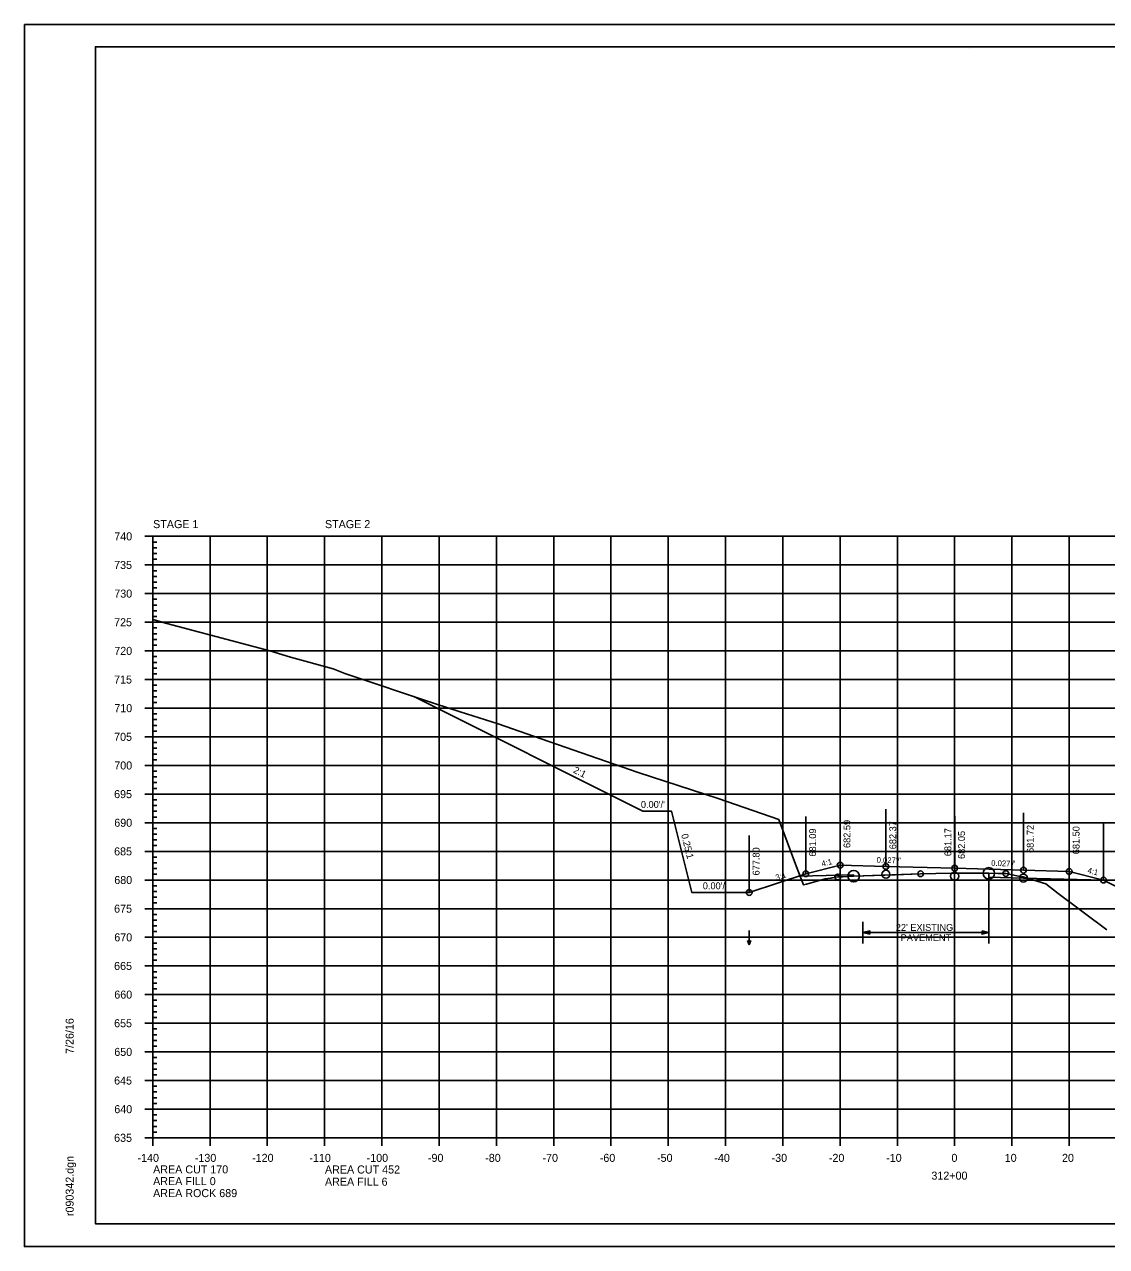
# Model space of a CAD drawing. Extents: x 1370515 to 1370849, y 383299 to 386073.
# Drawn here: x 1370515.4 to 1370704.3, y 385219.5 to 385432.8 of the extents above; entities that cross this region are included whole.
import ezdxf

# ---------------------------------------------------------------- set-up
doc = ezdxf.new("R2010")
doc.units = 0
for name, color, linetype in [('R_Alt Surface', 7, 'Continuous'), ('R_Axis', 7, 'Continuous'), ('R_Axis Annot', 7, 'Continuous'), ('R_Border', 7, 'Continuous'), ('R_Detour', 7, 'Continuous'), ('R_Exist Surface', 7, 'Continuous'), ('R_Fin Surface', 7, 'Continuous'), ('R_Grid', 7, 'Continuous'), ('R_No Plot', 7, 'Continuous'), ('R_ROW Annot', 7, 'Continuous'), ('R_Water', 7, 'Continuous'), ('R_Water Annot', 7, 'Continuous'), ('R_Xsect Elev', 7, 'Continuous'), ('R_Xsect Slope', 7, 'Continuous')]:
    doc.layers.add(name, color=color, linetype=linetype)

msp = doc.modelspace()

# ---------------------------------------------------------------- linework, layer by layer
at = {"layer": 'R_Alt Surface'}
msp.add_lwpolyline([(1370650.61, 385284.14), (1370660.16, 385284.33), (1370660.16, 385284.12), (1370671.86, 385284.55), (1370677.21, 385284.62), (1370683.77, 385284.62), (1370683.77, 385283.96), (1370689.8, 385283.79), (1370703.89, 385283.41)], dxfattribs=at)
at = {"layer": 'R_Axis'}
for p, q in [((1370536.4, 385343.45), (1370539.2, 385343.45)), ((1370537.8, 385238.45), (1370537.8, 385343.45)), ((1370537.8, 385342.45), (1370538.5, 385342.45)), ((1370537.8, 385341.45), (1370538.5, 385341.45)), ((1370537.8, 385340.45), (1370538.5, 385340.45)), ((1370537.8, 385339.45), (1370538.5, 385339.45)), ((1370536.4, 385338.45), (1370539.2, 385338.45)), ((1370537.8, 385337.45), (1370538.5, 385337.45)), ((1370537.8, 385336.45), (1370538.5, 385336.45)), ((1370537.8, 385335.45), (1370538.5, 385335.45)), ((1370536.4, 385333.45), (1370539.2, 385333.45)), ((1370537.8, 385334.45), (1370538.5, 385334.45)), ((1370537.8, 385332.45), (1370538.5, 385332.45)), ((1370537.8, 385331.45), (1370538.5, 385331.45)), ((1370537.8, 385330.45), (1370538.5, 385330.45)), ((1370536.4, 385328.45), (1370539.2, 385328.45)), ((1370537.8, 385329.45), (1370538.5, 385329.45)), ((1370537.8, 385327.45), (1370538.5, 385327.45)), ((1370537.8, 385326.45), (1370538.5, 385326.45)), ((1370537.8, 385325.45), (1370538.5, 385325.45)), ((1370537.8, 385324.45), (1370538.5, 385324.45)), ((1370536.4, 385323.45), (1370539.2, 385323.45)), ((1370537.8, 385322.45), (1370538.5, 385322.45)), ((1370537.8, 385321.45), (1370538.5, 385321.45)), ((1370537.8, 385320.45), (1370538.5, 385320.45)), ((1370536.4, 385318.45), (1370539.2, 385318.45)), ((1370537.8, 385319.45), (1370538.5, 385319.45)), ((1370537.8, 385317.45), (1370538.5, 385317.45)), ((1370537.8, 385316.45), (1370538.5, 385316.45)), ((1370537.8, 385315.45), (1370538.5, 385315.45)), ((1370536.4, 385313.45), (1370539.2, 385313.45)), ((1370537.8, 385314.45), (1370538.5, 385314.45)), ((1370537.8, 385312.45), (1370538.5, 385312.45)), ((1370537.8, 385311.45), (1370538.5, 385311.45)), ((1370537.8, 385310.45), (1370538.5, 385310.45)), ((1370537.8, 385309.45), (1370538.5, 385309.45)), ((1370536.4, 385308.45), (1370539.2, 385308.45)), ((1370537.8, 385307.45), (1370538.5, 385307.45)), ((1370537.8, 385306.45), (1370538.5, 385306.45)), ((1370537.8, 385305.45), (1370538.5, 385305.45)), ((1370536.4, 385303.45), (1370539.2, 385303.45)), ((1370537.8, 385304.45), (1370538.5, 385304.45)), ((1370537.8, 385302.45), (1370538.5, 385302.45)), ((1370537.8, 385301.45), (1370538.5, 385301.45)), ((1370536.4, 385298.45), (1370539.2, 385298.45)), ((1370537.8, 385300.45), (1370538.5, 385300.45)), ((1370537.8, 385299.45), (1370538.5, 385299.45)), ((1370537.8, 385297.45), (1370538.5, 385297.45)), ((1370537.8, 385296.45), (1370538.5, 385296.45)), ((1370537.8, 385295.45), (1370538.5, 385295.45)), ((1370537.8, 385294.45), (1370538.5, 385294.45)), ((1370536.4, 385293.45), (1370539.2, 385293.45)), ((1370537.8, 385292.45), (1370538.5, 385292.45)), ((1370537.8, 385291.45), (1370538.5, 385291.45)), ((1370537.8, 385290.45), (1370538.5, 385290.45)), ((1370536.4, 385288.45), (1370539.2, 385288.45)), ((1370537.8, 385289.45), (1370538.5, 385289.45)), ((1370537.8, 385287.45), (1370538.5, 385287.45)), ((1370537.8, 385286.45), (1370538.5, 385286.45)), ((1370536.4, 385283.45), (1370539.2, 385283.45)), ((1370537.8, 385285.45), (1370538.5, 385285.45)), ((1370537.8, 385284.45), (1370538.5, 385284.45)), ((1370537.8, 385282.45), (1370538.5, 385282.45)), ((1370537.8, 385281.45), (1370538.5, 385281.45)), ((1370537.8, 385280.45), (1370538.5, 385280.45)), ((1370537.8, 385279.45), (1370538.5, 385279.45)), ((1370536.4, 385278.45), (1370539.2, 385278.45)), ((1370537.8, 385277.45), (1370538.5, 385277.45)), ((1370537.8, 385276.45), (1370538.5, 385276.45)), ((1370537.8, 385275.45), (1370538.5, 385275.45)), ((1370536.4, 385273.45), (1370539.2, 385273.45)), ((1370537.8, 385274.45), (1370538.5, 385274.45)), ((1370537.8, 385272.45), (1370538.5, 385272.45)), ((1370537.8, 385271.45), (1370538.5, 385271.45)), ((1370537.8, 385270.45), (1370538.5, 385270.45)), ((1370537.8, 385269.45), (1370538.5, 385269.45)), ((1370536.4, 385268.45), (1370539.2, 385268.45)), ((1370537.8, 385267.45), (1370538.5, 385267.45)), ((1370537.8, 385266.45), (1370538.5, 385266.45)), ((1370537.8, 385265.45), (1370538.5, 385265.45)), ((1370537.8, 385264.45), (1370538.5, 385264.45)), ((1370536.4, 385263.45), (1370539.2, 385263.45)), ((1370537.8, 385262.45), (1370538.5, 385262.45)), ((1370537.8, 385261.45), (1370538.5, 385261.45)), ((1370537.8, 385260.45), (1370538.5, 385260.45)), ((1370536.4, 385258.45), (1370539.2, 385258.45)), ((1370537.8, 385259.45), (1370538.5, 385259.45)), ((1370537.8, 385257.45), (1370538.5, 385257.45)), ((1370537.8, 385256.45), (1370538.5, 385256.45)), ((1370537.8, 385255.45), (1370538.5, 385255.45)), ((1370537.8, 385254.45), (1370538.5, 385254.45)), ((1370536.4, 385253.45), (1370539.2, 385253.45)), ((1370537.8, 385252.45), (1370538.5, 385252.45)), ((1370537.8, 385251.45), (1370538.5, 385251.45)), ((1370537.8, 385250.45), (1370538.5, 385250.45)), ((1370537.8, 385249.45), (1370538.5, 385249.45)), ((1370536.4, 385248.45), (1370539.2, 385248.45)), ((1370537.8, 385247.45), (1370538.5, 385247.45)), ((1370537.8, 385246.45), (1370538.5, 385246.45)), ((1370537.8, 385245.45), (1370538.5, 385245.45)), ((1370536.4, 385243.45), (1370539.2, 385243.45)), ((1370537.8, 385244.45), (1370538.5, 385244.45)), ((1370537.8, 385242.45), (1370538.5, 385242.45)), ((1370537.8, 385241.45), (1370538.5, 385241.45)), ((1370537.8, 385240.45), (1370538.5, 385240.45)), ((1370537.8, 385237.05), (1370537.8, 385239.85)), ((1370537.8, 385239.45), (1370538.5, 385239.45)), ((1370547.8, 385237.05), (1370547.8, 385239.85)), ((1370557.8, 385237.05), (1370557.8, 385239.85)), ((1370567.8, 385237.05), (1370567.8, 385239.85)), ((1370577.8, 385237.05), (1370577.8, 385239.85)), ((1370587.8, 385237.05), (1370587.8, 385239.85)), ((1370597.8, 385237.05), (1370597.8, 385239.85)), ((1370607.8, 385237.05), (1370607.8, 385239.85)), ((1370617.8, 385237.05), (1370617.8, 385239.85)), ((1370627.8, 385237.05), (1370627.8, 385239.85)), ((1370637.8, 385237.05), (1370637.8, 385239.85)), ((1370647.8, 385237.05), (1370647.8, 385239.85)), ((1370657.8, 385237.05), (1370657.8, 385239.85)), ((1370667.8, 385237.05), (1370667.8, 385239.85)), ((1370677.8, 385237.05), (1370677.8, 385239.85)), ((1370687.8, 385237.05), (1370687.8, 385239.85)), ((1370697.8, 385237.05), (1370697.8, 385239.85)), ((1370536.4, 385238.45), (1370539.2, 385238.45)), ((1370537.8, 385238.45), (1370817.8, 385238.45))]:
    msp.add_line(p, q, dxfattribs=at)
at = {"layer": 'R_Border'}
for p, q in [((1370527.8, 385428.91), (1370843.98, 385428.91)), ((1370527.8, 385223.45), (1370527.8, 385428.91)), ((1370680.32, 385428.65), (1370680.32, 385428.65)), ((1370680.32, 385428.65), (1370680.32, 385428.65)), ((1370527.8, 385223.45), (1370527.8, 385223.45)), ((1370843.98, 385223.45), (1370527.8, 385223.45))]:
    msp.add_line(p, q, dxfattribs=at)
at = {"layer": 'R_Exist Surface'}
msp.add_lwpolyline([(1370537.8, 385328.93), (1370539.26, 385328.51), (1370539.31, 385328.5), (1370539.41, 385328.47), (1370558.21, 385323.45), (1370561.83, 385322.37), (1370569.27, 385320.31), (1370571.36, 385319.51), (1370586.97, 385314.24), (1370591.49, 385312.81), (1370598.08, 385310.72), (1370605.58, 385308.09), (1370622.53, 385302.22), (1370636.49, 385297.7), (1370647.09, 385293.99), (1370650.17, 385285.75), (1370651.41, 385282.61), (1370651.94, 385282.75), (1370655.2, 385283.64), (1370656.11, 385283.77), (1370656.22, 385283.78), (1370656.4, 385283.81), (1370657.39, 385283.98), (1370658.27, 385284.03), (1370660.16, 385284.12), (1370667.43, 385284.36), (1370671.86, 385284.55), (1370677.21, 385284.62), (1370683.77, 385284.62), (1370685.31, 385284.61), (1370686.74, 385284.58), (1370688.97, 385284.15), (1370689.78, 385284.03), (1370692.39, 385283.19), (1370693.69, 385282.76), (1370695.86, 385281.1), (1370704.37, 385274.76)], dxfattribs=at)
at = {"layer": 'R_Fin Surface'}
msp.add_lwpolyline([(1370583.36, 385315.46), (1370623.38, 385295.45), (1370628.38, 385295.45), (1370631.93, 385281.25), (1370641.93, 385281.25), (1370651.8, 385284.54), (1370657.8, 385286.04), (1370665.8, 385285.82), (1370677.8, 385285.5), (1370689.8, 385285.17), (1370697.8, 385284.95), (1370703.8, 385283.45), (1370772.26, 385249.22), (1370802.26, 385249.22), (1370815.36, 385253.59)], dxfattribs=at)
at = {"layer": 'R_Grid'}
for p, q in [((1370537.8, 385343.45), (1370817.8, 385343.45)), ((1370537.8, 385238.45), (1370537.8, 385343.45)), ((1370547.8, 385238.45), (1370547.8, 385343.45)), ((1370557.8, 385238.45), (1370557.8, 385343.45)), ((1370567.8, 385238.45), (1370567.8, 385343.45)), ((1370577.8, 385238.45), (1370577.8, 385343.45)), ((1370587.8, 385238.45), (1370587.8, 385343.45)), ((1370597.8, 385238.45), (1370597.8, 385343.45)), ((1370607.8, 385238.45), (1370607.8, 385343.45)), ((1370617.8, 385238.45), (1370617.8, 385343.45)), ((1370627.8, 385238.45), (1370627.8, 385343.45)), ((1370637.8, 385238.45), (1370637.8, 385343.45)), ((1370647.8, 385238.45), (1370647.8, 385343.45)), ((1370657.8, 385238.45), (1370657.8, 385343.45)), ((1370667.8, 385238.45), (1370667.8, 385343.45)), ((1370677.8, 385238.45), (1370677.8, 385343.45)), ((1370687.8, 385238.45), (1370687.8, 385343.45)), ((1370697.8, 385238.45), (1370697.8, 385343.45)), ((1370537.8, 385338.45), (1370817.8, 385338.45)), ((1370537.8, 385333.45), (1370817.8, 385333.45)), ((1370537.8, 385328.45), (1370817.8, 385328.45)), ((1370537.8, 385323.45), (1370817.8, 385323.45)), ((1370537.8, 385318.45), (1370817.8, 385318.45)), ((1370537.8, 385313.45), (1370817.8, 385313.45)), ((1370537.8, 385308.45), (1370817.8, 385308.45)), ((1370537.8, 385303.45), (1370817.8, 385303.45)), ((1370537.8, 385298.45), (1370817.8, 385298.45)), ((1370537.8, 385293.45), (1370817.8, 385293.45)), ((1370537.8, 385288.45), (1370817.8, 385288.45)), ((1370537.8, 385283.45), (1370817.8, 385283.45)), ((1370537.8, 385278.45), (1370817.8, 385278.45)), ((1370537.8, 385273.45), (1370817.8, 385273.45)), ((1370537.8, 385268.45), (1370817.8, 385268.45)), ((1370537.8, 385263.45), (1370817.8, 385263.45)), ((1370537.8, 385258.45), (1370817.8, 385258.45)), ((1370537.8, 385253.45), (1370817.8, 385253.45)), ((1370537.8, 385248.45), (1370817.8, 385248.45)), ((1370537.8, 385243.45), (1370817.8, 385243.45)), ((1370537.8, 385238.45), (1370817.8, 385238.45))]:
    msp.add_line(p, q, dxfattribs=at)
at = {"layer": 'R_No Plot'}
for p, q in [((1370515.4, 385432.81), (1370848.73, 385432.81)), ((1370515.4, 385219.47), (1370848.73, 385219.47))]:
    msp.add_line(p, q, dxfattribs=at)
for points in [[(1370515.39, 385432.81), (1370848.73, 385432.81), (1370848.73, 385219.47), (1370515.39, 385219.47)], [(1370761.72, 385428.91), (1370761.72, 385419.03), (1370797.45, 385419.03), (1370797.45, 385416.11), (1370820.65, 385416.11), (1370820.65, 385392.9), (1370843.98, 385392.9), (1370843.98, 385223.45), (1370527.8, 385223.45), (1370527.8, 385428.91)]]:
    msp.add_lwpolyline(points, close=True, dxfattribs=at)
for centre, radius in [((1370657.8, 385286.04), 0.5), ((1370665.8, 385285.82), 0.5), ((1370677.8, 385285.5), 0.5), ((1370683.77, 385284.62), 1), ((1370689.8, 385285.17), 0.5), ((1370651.8, 385284.54), 0.5), ((1370651.8, 385284.54), 0.5), ((1370657.39, 385283.98), 0.5), ((1370660.16, 385284.12), 1), ((1370665.8, 385284.45), 0.7), ((1370671.86, 385284.55), 0.5), ((1370677.8, 385284.12), 0.7), ((1370677.8, 385284.12), 0.7), ((1370686.74, 385284.58), 0.5), ((1370689.8, 385283.79), 0.7), ((1370697.8, 385284.95), 0.5), ((1370703.8, 385283.45), 0.5), ((1370703.8, 385283.45), 0.5), ((1370641.93, 385281.25), 0.5)]:
    msp.add_circle(centre, radius, dxfattribs=at)
at = {"layer": 'R_ROW Annot'}
for p, q in [((1370661.79, 385272.39), (1370661.79, 385276.16)), ((1370683.79, 385272.39), (1370683.79, 385276.16)), ((1370683.79, 385274.28), (1370661.79, 385274.28))]:
    msp.add_line(p, q, dxfattribs=at)
for points in [[(1370662.99, 385273.98), (1370661.79, 385274.28), (1370662.99, 385274.58)], [(1370682.59, 385274.58), (1370683.79, 385274.28), (1370682.59, 385273.98)]]:
    msp.add_lwpolyline(points, close=True, dxfattribs=at)
at = {"layer": 'R_Water'}
msp.add_line((1370683.79, 385284.6), (1370683.79, 385276.16), dxfattribs=at)
at = {"layer": 'R_Water Annot'}
for p, q in [((1370641.94, 385272.13), (1370641.66, 385272.9)), ((1370641.94, 385274.64), (1370641.94, 385272.13)), ((1370641.94, 385272.13), (1370642.22, 385272.9))]:
    msp.add_line(p, q, dxfattribs=at)
at = {"layer": 'R_Xsect Elev'}
for p, q in [((1370651.8, 385284.54), (1370651.8, 385294.54)), ((1370657.8, 385286.04), (1370657.8, 385296.04)), ((1370665.8, 385285.82), (1370665.8, 385295.82)), ((1370677.8, 385284.12), (1370677.8, 385294.12)), ((1370677.82, 385284.61), (1370677.82, 385294.61)), ((1370689.8, 385285.17), (1370689.8, 385295.17)), ((1370697.8, 385284.95), (1370697.8, 385294.95)), ((1370703.8, 385283.45), (1370703.8, 385293.45)), ((1370641.93, 385281.25), (1370641.93, 385291.25))]:
    msp.add_line(p, q, dxfattribs=at)

# ---------------------------------------------------------------- texts
at = {"layer": 'R_Axis'}
msp.add_text('-', height=0.0001, dxfattribs=at).set_placement((1370537.8, 385238.45))
at = {"layer": 'R_Axis Annot'}
for s, p in [('STAGE 1', (1370537.86, 385344.88)), ('STAGE 2', (1370567.86, 385344.88)), ('740', (1370531.08, 385342.75)), ('735', (1370531.05, 385337.75)), ('730', (1370531.08, 385332.75)), ('725', (1370531.05, 385327.75)), ('720', (1370531.08, 385322.75)), ('715', (1370531.05, 385317.75)), ('710', (1370531.08, 385312.75)), ('705', (1370531.05, 385307.75)), ('700', (1370531.08, 385302.75)), ('695', (1370531.05, 385297.75)), ('690', (1370531.08, 385292.75)), ('685', (1370531.05, 385287.75)), ('680', (1370531.08, 385282.75)), ('675', (1370531.05, 385277.75)), ('670', (1370531.08, 385272.75)), ('665', (1370531.05, 385267.75)), ('660', (1370531.08, 385262.75)), ('655', (1370531.05, 385257.75)), ('650', (1370531.08, 385252.75)), ('645', (1370531.05, 385247.75)), ('640', (1370531.08, 385242.75)), ('635', (1370531.05, 385237.75)), ('-140', (1370535.14, 385234.25)), ('-130', (1370545.14, 385234.25)), ('-120', (1370555.14, 385234.25)), ('-110', (1370565.14, 385234.25)), ('-100', (1370575.14, 385234.25)), ('-90', (1370585.84, 385234.25)), ('-80', (1370595.84, 385234.25)), ('-70', (1370605.84, 385234.25)), ('-60', (1370615.84, 385234.25)), ('-50', (1370625.84, 385234.25)), ('-40', (1370635.84, 385234.25)), ('-30', (1370645.84, 385234.25)), ('-20', (1370655.84, 385234.25)), ('-10', (1370665.84, 385234.25)), ('0', (1370677.24, 385234.25)), ('10', (1370686.54, 385234.25)), ('20', (1370696.54, 385234.25)), ('AREA CUT 170', (1370537.86, 385232.24)), ('AREA CUT 452', (1370567.86, 385232.22)), ('312+00', (1370673.74, 385231.15)), ('AREA FILL 0', (1370537.86, 385230.19)), ('AREA FILL 6', (1370567.86, 385230.09)), ('AREA ROCK 689', (1370537.86, 385228.1))]:
    msp.add_text(s, height=1.4, dxfattribs=at).set_placement(p)
at = {"layer": 'R_Border'}
for s, p in [('7/26/16', (1370523.99, 385253.09)), ('r090342.dgn', (1370523.99, 385224.78))]:
    msp.add_text(s, height=1.4, rotation=90, dxfattribs=at).set_placement(p)
at = {"layer": 'R_Detour'}
msp.add_text('2:1', height=1.2, rotation=333.4349, dxfattribs=at).set_placement((1370611.1, 385302.26))
at = {"layer": 'R_Fin Surface'}
for p in [(1370623.02, 385296.04), (1370633.83, 385281.84)]:
    msp.add_text("0.00'/'", height=1.2, dxfattribs=at).set_placement(p)
msp.add_text('0.25:1', height=1.2, rotation=284.0362, dxfattribs=at).set_placement((1370630.04, 385291.37))
at = {"layer": 'R_No Plot'}
for p in [(1370539.21, 385328.46), (1370569.23, 385320.26), (1370598.03, 385310.67), (1370622.48, 385302.17), (1370647.05, 385293.94), (1370655.16, 385283.59), (1370656.18, 385283.73), (1370689.74, 385283.98), (1370651.37, 385282.56), (1370693.65, 385282.71)]:
    msp.add_text('+', height=0.1, dxfattribs=at).set_placement(p)
at = {"layer": 'R_ROW Annot'}
for s, p in [("22' EXISTING", (1370667.52, 385274.58)), ('PAVEMENT', (1370668.37, 385272.78))]:
    msp.add_text(s, height=1.2, dxfattribs=at).set_placement(p)
at = {"layer": 'R_Xsect Elev'}
for s, p in [('681.09', (1370653.6, 385287.54)), ('682.59', (1370659.6, 385289.04)), ('682.37', (1370667.6, 385288.82)), ('681.17', (1370677.22, 385287.61)), ('681.72', (1370691.6, 385288.17)), ('681.50', (1370699.6, 385287.95)), ('682.05', (1370679.6, 385287.12)), ('677.80', (1370643.73, 385284.25))]:
    msp.add_text(s, height=1.2, rotation=90, dxfattribs=at).set_placement(p)
at = {"layer": 'R_Xsect Slope'}
for s, rotation, p in [('4:1', 14.0362, (1370654.68, 385285.78)), ("0.027'/'", 358.4387, (1370664.17, 385286.47)), ("0.027'/'", 358.4387, (1370684.17, 385285.92)), ('3:1', 18.4349, (1370646.71, 385283.37)), ('4:1', 345.9638, (1370700.92, 385284.69))]:
    msp.add_text(s, height=1, rotation=rotation, dxfattribs=at).set_placement(p)

doc.saveas('drawing.dxf')
